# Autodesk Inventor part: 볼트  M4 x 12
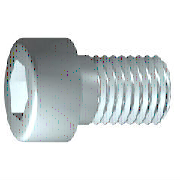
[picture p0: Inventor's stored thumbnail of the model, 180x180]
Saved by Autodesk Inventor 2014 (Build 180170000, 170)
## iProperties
IsCustomPart: 0
Created: 2015-12
Part Number: 볼트  M4 x 12
Material: 일반
Description: 6각머리 태핑 나사
Document SubType Name: Modeling
Standard: KS B 1003
Designer: mdu
Standards Organization: KS
Language: ko-KR
Size Designation: M 4 x 12
Categories: <MemberInstance><Categories><Category DisplayName="조임쇠" InternalName="e4da775c-781d-43d5-af7c-5136215cf5a6" Mnemonic="FSTN"><Category DisplayName="볼트" InternalN
Density: 1 g/cm^3
Mass: 0.284306 g
Surface Area: 3.30853 cm^2
Volume: 0.284306 cm^3
Appearance: Default
Author: mdu
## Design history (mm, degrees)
sketch "스케치1"
  geometry: L1 (-1, 0)-(12, 0); L2 (12, 0)-(12, 2); L3 (12, 2)-(1.75, 2); L4 (1.75, 2)-(1.32, 2); L5 (1.32, 2)-(0, 2); L6 (0, 2)-(0, 3.5); L7 (0, 3.5)-(-4, 3.5); L8 (-4, 3.5)-(-4, 1.732); L9 (-4, 1.732)-(-2, 1.732); L10 (-2, 1.732)-(-1, 0); L11 (-7.2, 0)-(15.2, 0) reference; L12 (0, -0.7)-(0, 4.2) reference; L13 (1.75, 2)-(0, 2)
  constraints: 22 end point, 6 parallel, 2 collinear, 2 perpendicular, 1 horizontal, 1 point on line
  dimensions: "d1" = 10.25 distance from line of L3.end L2 (= GEL); "d2" = 0.42952 distance of L4.end L3.end (computed from GAL); "d3" = 4 distance between parallel lines of L8 L6 (= KOH); "d4" = 2 distance of L8.end L9.end (= INTI); "d5" = 60 deg angle of L10 L1; "d6" = 4 diameter of L3 L1 (= GD); "d7" = 4 diameter of L5 L1 (= BDM); "d8" = 3.4641 diameter of L9 L1 (= 1.1547 x SW); "d9" = 7 diameter of L7 L1 (= KOD); "d26" = 12 distance between parallel lines of L12 L2 (= NLG)
revolve "본체" sketch "스케치1" stored, may be unused: angle "d10" = 90 deg
sketch "스케치2"
  geometry: L1 (0, -4.9)-(0, 4.9) reference; L2 (-4.9, 0)-(4.9, 0) reference; L3 (1.732, 0)-(0.866, -1.5); L4 (0.866, -1.5)-(-0.866, -1.5); L5 (-0.866, -1.5)-(-1.732, 0); L6 (-1.732, 0)-(-0.866, 1.5); L7 (-0.866, 1.5)-(0.866, 1.5); L8 (0.866, 1.5)-(1.732, 0); 2 further points
  constraints: 12 end point, 1 coincident, 1 horizontal alignment, 1 point on line, 12 other
extrude "슬롯" join sketch "스케치2" stored distance "d11" = 10; taper "d12" = 0 deg
workplane "Work Plane1"
fillet "Fillet2" dims "d30" = 0.1 (= R)
body "Solid1"
fillet "모깎기1" dims "d17" = 0.4 (= RR)
feature "스레드" dims "d13" = 10.25 (= GEL), "d14" = 0
chamfer "모따기1" distance "d15" = 0.42941 (= -0.5 x SPD + 0.5 x GD); stored, may be unused: second distance "d16" = 0.42941 (= GUL), angle "d27" = 45 deg
other parameters: "GD" = 4 (= NND) [user parameter; used in 2 equation terms], "NLG" = 12 [user parameter; used in 1 equation term], "GEL" = 10.25 [user parameter; used in 2 equation terms], "KOD" = 7 [user parameter; used in 1 equation term], "KOH" = 4 [user parameter; used in 1 equation term], "INTI" = 2 [user parameter; used in 1 equation term], "GAL" = 0.42941 (= 0.61345 x PTC) [user parameter; used in 1 equation term], "GUL" = 0.42941 (= 0.61345 x PTC) [user parameter; used in 1 equation term], "BDM" = 4 (= NND) [user parameter; used in 1 equation term], "SW" = 3 [user parameter; used in 2 equation terms], "RR" = 0.4 [user parameter; used in 1 equation term], "SPD" = 3.14117 (= NND - 1.2269 x PTC) [user parameter; used in 1 equation term], "d19" = 0, "d28" = 0, "d29" = 0, "R" = 0.1 [user parameter; used in 1 equation term], "PHH" = 0.2 [user parameter], "GD1" = 3.14117 (= THREADDIA - 1.2269 x PTC) [user parameter], "THREADDIA" = 4 [user parameter; used in 1 equation term], "FAWI" = 45 deg [user parameter], "TPU" = 14.28571 (computed from PTC) [user parameter], "PTC" = 0.7 [user parameter; used in 5 equation terms], "NND" = 4 [user parameter; used in 3 equation terms], "TOA" = 30 deg [user parameter], "E0" = 3.465 (= 1.155 x SW) [user parameter]
